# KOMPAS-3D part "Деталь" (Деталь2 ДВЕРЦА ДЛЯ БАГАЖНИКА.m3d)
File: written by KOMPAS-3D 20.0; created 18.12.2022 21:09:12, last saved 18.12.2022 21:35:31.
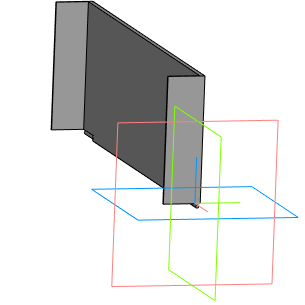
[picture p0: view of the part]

Document properties: Полное имя файла: C:\Users\Семья\Desktop\ДЕТАЛИ ДЛЯ СБОРЩИКА БОРЩЕВИКА\Деталь2 ДВЕРЦА ДЛЯ БАГАЖНИКА.m3d

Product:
- Part/product: Деталь
    Масса: 0.0610303
  - Body: Тело 1
      Масса: 0.0642166

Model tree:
1. Эскиз:1
2. Элемент выдавливания:1
     Расстояние 1 = 1
3. Элемент выдавливания:2  (with: Элемент выдавливания:1)
     Расстояние 1 = 0.5
4. Эскиз:2  (with: Элемент выдавливания:1, Элемент выдавливания:2)
5. Элемент выдавливания:3
     Расстояние 1 = 2
6. Эскиз:3  (with: Элемент выдавливания:3)
7. Элемент выдавливания:4
     Расстояние 1 = 10
8. Эскиз:4  (with: Элемент выдавливания:3)
9. Элемент выдавливания:5
     Расстояние 1 = 10
10. Элемент выдавливания:6  (with: Элемент выдавливания:1)
     Расстояние 1 = 0.5
11. Элемент выдавливания:7  (with: Элемент выдавливания:1)
     Расстояние 1 = 0.5
12. Эскиз:5  (with: Элемент выдавливания:1, Элемент выдавливания:7)
13. Элемент выдавливания:8
     Расстояние 1 = 10
14. Эскиз:6  (with: Элемент выдавливания:3, Элемент выдавливания:4)
15. Элемент выдавливания:9
     Расстояние 2 = 110.5
16. Элемент выдавливания:10  (with: Элемент выдавливания:8)
     Расстояние 2 = 0.5
17. Элемент выдавливания:11  (with: Элемент выдавливания:8)
     Расстояние 2 = 0.5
